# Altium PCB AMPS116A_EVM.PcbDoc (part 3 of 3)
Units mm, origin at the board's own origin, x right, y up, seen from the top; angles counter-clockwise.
Board outline 95 x 85 mm, 4 copper layers (Top Layer, Mid-Layer 1, Mid-Layer 2, Bottom Layer), stack 1.554 mm thick; 252 components, 134 nets, 806 pads, 625 vias.
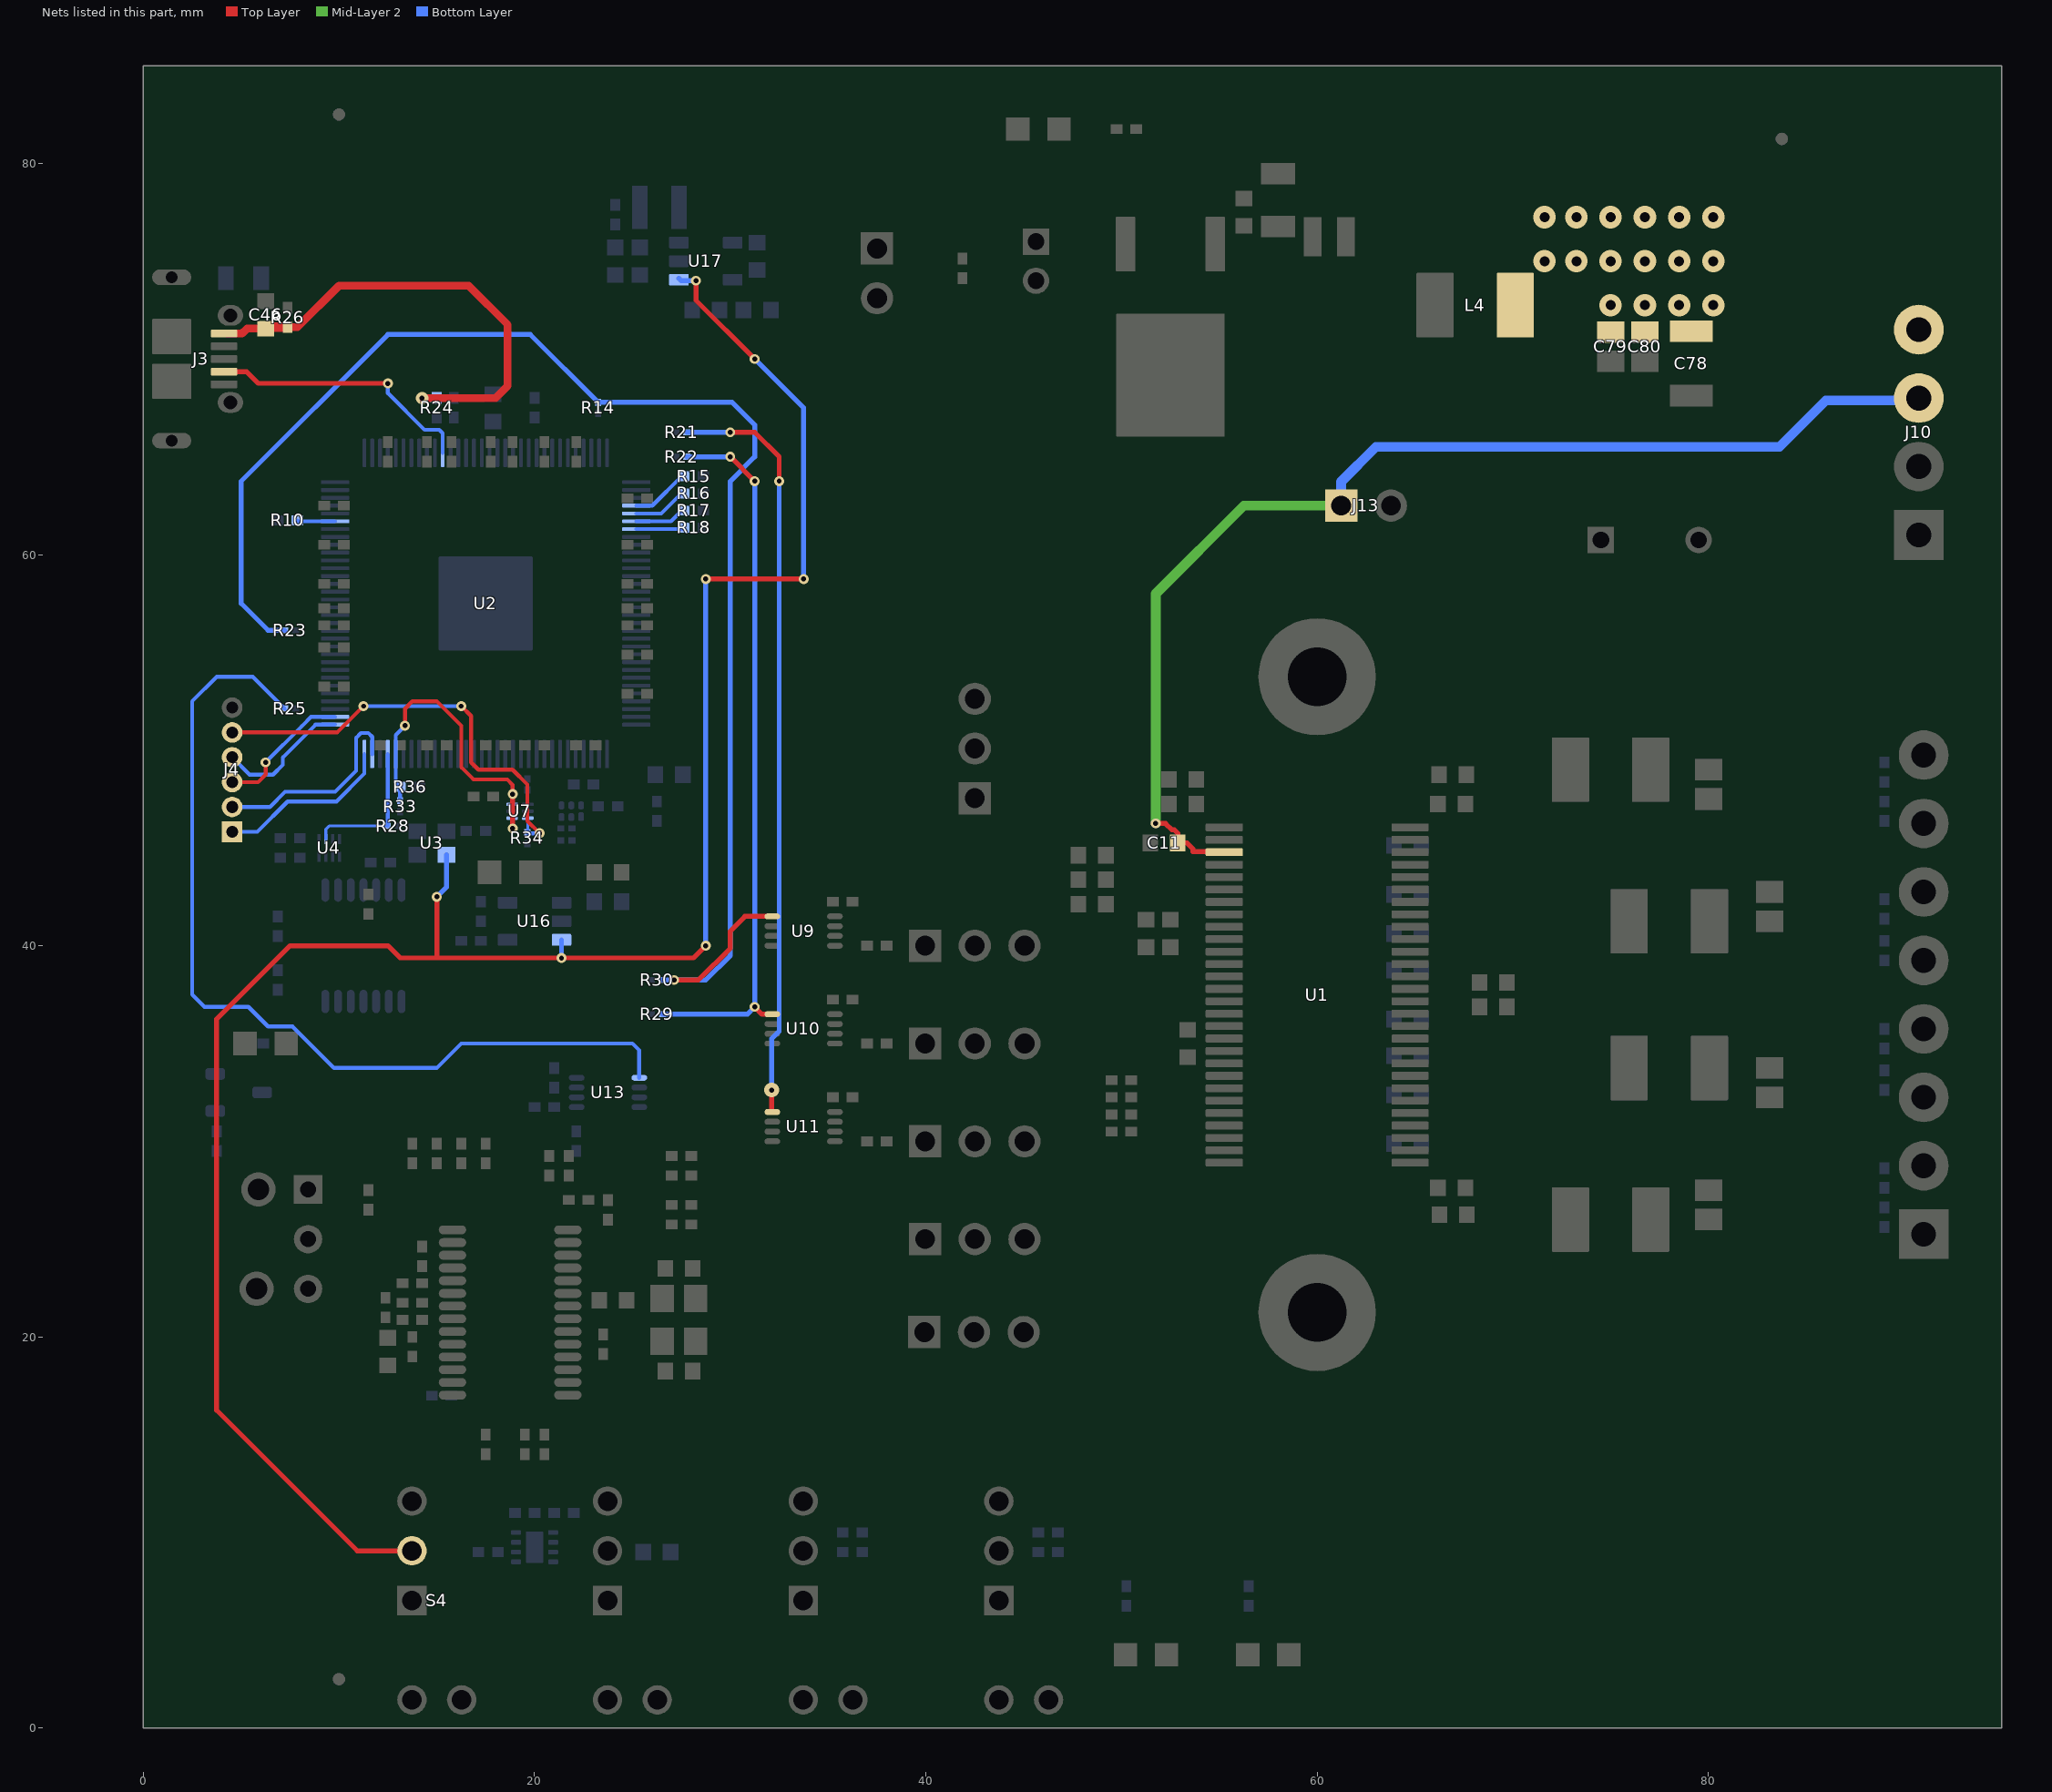
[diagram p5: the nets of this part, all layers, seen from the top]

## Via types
v1: diameter 0.508, hole 0.254, Top Layer to Bottom Layer, tented both sides, 516 vias
v2: diameter 0.762, hole 0.254, Top Layer to Bottom Layer, tented both sides, 30 vias
v3: diameter 1.143, hole 0.508, Top Layer to Bottom Layer, tented both sides, 28 vias
v4: diameter 0.889, hole 0.254, Top Layer to Bottom Layer, tented both sides, 24 vias
v5: diameter 0.6, hole 0.3, Top Layer to Bottom Layer, 12 vias
v6: diameter 0.635, hole 0.254, Top Layer to Bottom Layer, tented both sides, 9 vias
v7: diameter 6, hole 3.25, Top Layer to Bottom Layer, 4 vias
v8: diameter 0.5, hole 0.2, Top Layer to Bottom Layer, 2 vias

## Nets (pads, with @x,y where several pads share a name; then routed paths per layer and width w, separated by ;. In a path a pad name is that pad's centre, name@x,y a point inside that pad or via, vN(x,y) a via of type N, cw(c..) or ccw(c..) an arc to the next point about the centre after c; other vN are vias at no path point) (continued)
USB-EN: S4.2 U3.1 U16.3 U17.1 | length 108.6
  Top Layer w0.25: S4.2@13.73,9.065 10.935,9.065 3.75,16.25 3.75,36.25 7.5,40 12.5,40 13.125,39.375 15,39.375 ; v1(15,42.5) 15,39.375 ; v1(28.25,74) 28.25,73 v1(31.25,70) ; v1(28.75,40) 28.125,39.375 v1(21.375,39.375) 15,39.375 ; v1(28.75,58.75) v1(33.75,58.75)
  Bottom Layer w0.25: v1(15,42.5) 15.5,43 U3.1@15.5,44.65 ; v1(21.375,39.375) U16.3@21.375,40.3 ; U17.1@27.375,74.125 27.5,74 v1(28.25,74) ; v1(28.75,40) v1(28.75,58.75) ; v1(31.25,70) 33.75,67.5 v1(33.75,58.75)
USB-ID: J3.4 U2.43 | length 13.6
  Top Layer w0.25: J3.4@4.3,69.35 5.275,69.35 5.875,68.75 v1(12.5,68.75)
  Bottom Layer w0.2: v1(12.5,68.75) 12.5,68.25 14.375,66.375 15.125,66.375 15.3,66.2 U2.43@15.3,65.2
VBAT: C11.2 J10.3 J13.1 U1.3 | length 60
  Top Layer w0.254: v1(51.75,46.256) 52.244,46.256 ; 52.25,46.25 52.579,45.921 52.704,45.921 52.875,45.75 C11.2@52.875,45.25 53.358,45.25 53.647,44.96 53.647,44.803 U1.3@55.25,44.803
  Mid-Layer 2 w0.5: v1(51.75,46.256) 51.75,58 56.25,62.5 J13.1@61.23,62.5
  Bottom Layer w0.5: J13.1@61.23,62.5 61.23,63.73 63,65.5 83.625,65.5 86,67.875 J10.3@90.75,67.875
VBUS-IN: C46.1 J3.1 R24.2 R26.2 | length 24.4
  Top Layer w0.4: J3.1@4.3,71.3 5.05,71.3 5.3,71.55 C46.1@6.25,71.55 ; 7.625,71.625 7.875,71.625 10,73.75 16.625,73.75 18.625,71.75 18.625,68.625 18,68 v6(14.25,68)
  Top Layer w0.5: C46.1@6.25,71.55 6.325,71.625 R26.2@7.375,71.625
  Bottom Layer w0.4: v6(14.25,68) R24.2@15,68
VIN: C78.2 C79.2 C80.1 J10.4 L4.1
  other v3: 75,72.75 76.75,72.75 78.5,72.75 80.25,72.75 71.625,75 73.25,75 75,75 76.75,75 78.5,75 80.25,75 71.625,77.25 73.25,77.25 75,77.25 76.75,77.25 78.5,77.25 80.25,77.25
X-24M: R28.2 U2.125 U4.2 | length 7.4
  Bottom Layer w0.15: U4.2@9.325,45.45 9.325,45.95 9.5,46.125 R28.2@12.47,46.125
  Bottom Layer w0.2: R28.2@12.47,46.125 12.5,46.155 U2.125@12.5,49.8
X-BCLK: R22.2 R29.2 U10.1 | length 36.8
  Top Layer w0.25: v1(30,65) v1(31.25,63.75) ; v1(31.25,36.875) 31.625,36.5 U10.1@32.15,36.5 ; U10.1@32.225,36.5 U10.1@32.25,36.5
  Bottom Layer w0.25: R29.2@26.53,36.5 30.875,36.5 v1(31.25,36.875) v1(31.25,63.75) ; R22.2@27.78,65 v1(30,65)
X-DOUT: R25.2 U13.1 | length 47.4
  Bottom Layer w0.2: R25.2@7.22,52.125 5.595,53.75 3.75,53.75 2.5,52.5 2.5,37.5 3.125,36.875 5.375,36.875 6.375,35.875 7.625,35.875 9.75,33.75 15,33.75 16.25,35 25,35 25.35,34.65 U13.1@25.35,33.25
X-LRCK: R21.2 U11.1 | length 38.9
  Top Layer w0.25: v1(30,66.25) 31.25,66.25 32.5,65 v1(32.5,63.75) ; v2(32.125,32.625) 32.125,31.6 U11.1@32.225,31.5
  Bottom Layer w0.25: R21.2@27.78,66.25 v1(30,66.25) ; v2(32.125,32.625) 32.125,35.25 32.5,35.625 v1(32.5,63.75)
X-MCLK: R14.2 R23.2 R30.2 U9.1 | length 78.8
  Top Layer w0.25: v1(27.125,38.25) 28.375,38.25 30,39.875 30,40.75 30.75,41.5 U9.1@32.15,41.5
  Bottom Layer w0.25: R23.2@7.22,56.125 6.375,56.125 5,57.5 5,63.75 12.5,71.25 19.78,71.25 R14.2@23.25,67.78 30.095,67.78 31.25,66.625 31.25,65 30,63.75 30,39.5 28.75,38.25 v1(27.125,38.25) R30.2@26.53,38.25
X-QSPI-CS: R10.2 U2.27 | length 1.9
  Bottom Layer w0.2: R10.2@7.875,61.75 7.925,61.7 U2.27@9.8,61.7
X-RSTN: R33.2 R36.2 U2.124 U7.4 U7.6 | length 17
  Top Layer w0.2: v1(13.375,51.25) 13.375,52.125 13.75,52.5 15,52.5 16.25,51.25 16.25,49.125 16.875,48.5 18.6,48.5 18.875,48.225 v1(18.875,47.75)
  Top Layer w0.25: v1(18.875,46) v1(18.875,47.75)
  Bottom Layer w0.15: U7.4@18.85,46.525 18.875,46.5 v1(18.875,46) ; U7.6@18.85,47.225 18.875,47.25 v1(18.875,47.75)
  Bottom Layer w0.2: R33.2@13.125,47.405 R36.2@13.125,48.125 12.9,48.35 U2.124@12.9,49.8 12.9,50.775 v1(13.375,51.25)
X-SPI-SS0: R15.1 U2.68 | length 3
  Bottom Layer w0.2: U2.68@25.2,62.5 26.02,62.5 27.52,64 R15.1@27.625,64
X-SPI-SS1: R16.1 U2.69 | length 2.8
  Bottom Layer w0.2: U2.69@25.2,62.1 26.475,62.1 27.5,63.125 R16.1@27.625,63.125
X-SPI-SS2: R17.1 U2.70 | length 2.7
  Bottom Layer w0.2: U2.70@25.2,61.7 26.976,61.7 27.526,62.25 R17.1@27.625,62.25
X-SPI-SS3: R18.1 U2.71 | length 2.5
  Bottom Layer w0.2: U2.71@25.2,61.3 27.55,61.3 R18.1@27.625,61.375
X-TCK: J4.1 U2.128 | length 9
  Bottom Layer w0.2: J4.1@4.54,45.825 5.825,45.825 7.375,47.375 9.875,47.375 11.3,48.8 U2.128@11.3,49.8
X-TDI: J4.3 U2.2 | length 7
  Top Layer w0.2: J4.3@4.54,48.365 5.865,48.365 6.25,48.75 v1(6.25,49.375)
  Bottom Layer w0.2: v1(6.25,49.375) 8.125,51.25 8.575,51.7 U2.2@9.8,51.7
X-TDO: J4.4 U2.1 | length 6.9
  Bottom Layer w0.2: J4.4@4.54,49.635 5.425,48.75 6.625,48.75 7.125,49.25 7.125,49.625 8.8,51.3 U2.1@9.8,51.3
X-TMS: J4.2 U2.127 | length 10.7
  Bottom Layer w0.2: J4.2@4.54,47.095 6.47,47.095 7.25,47.875 9.809,47.875 10.875,48.941 10.875,50.625 11.125,50.875 11.5,50.875 11.7,50.675 U2.127@11.7,49.8
X-TRSTN: J4.5 R34.2 U7.3 | length 22.8
  Top Layer w0.2: J4.5@4.54,50.905 9.905,50.905 v1(11.25,52.25) ; v1(16.25,52.25) 16.75,51.75 16.75,49.375 17.125,49 18.875,49 19.625,48.25 19.625,46.375 v1(20.25,45.75)
  Bottom Layer w0.15: R34.2@19.625,45.78 19.65,45.805 U7.3@19.65,46.525
  Bottom Layer w0.2: v1(11.25,52.25) v1(16.25,52.25) ; R34.2@19.625,45.78 19.655,45.75 v1(20.25,45.75)
pads on no net: FID1.1 FID2.1 FID3.1 FID4.1 FID5.1 FID6.1 S1.1 S2.1 SH1.0 SH2.0 SH3.0 SH4.0 SH5.0 SH6.0 U2.4 U2.5 U2.7 U2.8 U2.9 U2.10 U2.12 U2.15 U2.18 U2.20 U2.21 U2.22 U2.23 U2.25 U2.26 U2.28 U2.30 U2.31 U2.32 U2.33 U2.34 U2.35 U2.39 U2.40 U2.50 U2.51 U2.53 U2.54 U2.57 U2.58 U2.59 U2.61 U2.62 U2.65 U2.72 U2.74 U2.75 U2.76 U2.77 U2.79 U2.82 U2.84 U2.85 U2.86 U2.88 U2.89 U2.90 U2.91 U2.93 U2.94 U2.95 U2.96 U2.97 U2.98 U2.99 U2.100 U2.106 U2.107 U2.108 U2.109 U2.112 U2.113 U2.114 U2.115 U2.117 U2.118 U2.119 U2.121 U2.122 U4.6 U5.4 U5.8 U5.14 U9.3 U10.3 U11.3 U12.1 U12.2 U12.3 U12.9 U12.15 U12.16 U12.17 U12.18 U13.3 U14.0 U15.4@50.505,70.35 U15.4@50.505,71.53 U15.4@51.835,70.35 U15.4@51.835,71.53 U15.4@53.165,70.35 U15.4@53.165,71.53 U15.4@54.495,70.35 U15.4@54.495,71.53 U15.5 U15.6 U15.7

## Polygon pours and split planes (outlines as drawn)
PVDD on Mid-Layer 2 "PVDD Copper Layer 3" (solid, remove dead copper, pour order 152): 68.75,70 68.75,68.25 74.75,62.25 75.75,62.25 76,62 76,56 65.75,45.75 65.75,26.875 65.375,26.5 64,26.5 60,30.5 60,43.75 59.25,44.5 56.75,44.5 56.375,44.875 56.375,46 56.75,46.375 60.125,46.375 70.75,57 70.75,60 69.5,61.25 63.75,61.25 62.875,62.125 62.875,70.125 63.625,70.875 67.875,70.875
3.3V on Mid-Layer 2 "3.3V Copper Layer 3" (solid, remove dead copper, pour order 180): 39.375,77.5 16.5,77.5 5,66 5,57 6.25,55.75 6.25,41.25 7.5,40 27.5,40 29.875,42.375 29.875,59.875 40.375,70.375 40.375,76.5
1.0V on Mid-Layer 2 "1.0V Copper Layer 3" (solid, remove dead copper, pour order 177): 22.75,76.25 20.875,76.25 20.5,75.875 20.5,66.75 20,66.25 11.25,66.25 8.75,63.75 8.75,51.25 11,49 24,49 26.25,51.25 26.25,61 26,61.25 24.5,61.25 24.25,61 24.25,51.75 23.25,50.75 11.75,50.75 10.75,51.75 10.75,63 12.25,64.5 22.25,64.5 23.125,65.375 23.125,75.875
GND on Mid-Layer 2 "GND Copper Layer 3" (solid, remove dead copper, pour order 206): 0.5,83 2,84.5 93,84.5 94.5,83 94.5,2 93,0.5 2,0.5 0.5,2
VIN on Top Layer "VIN Top Layer" (solid, remove dead copper, pour order 204): 71.5,78.125 88.625,78.125 92.25,74.5 92.25,70.375 91.875,70 89.375,70 88.5,70.875 70.5,70.875 70.5,77.125
OUT3- on Top Layer "OUT3- Top Copper" (solid, remove dead copper, pour order 197): 79.85,43 81.75,43 81.75,42.475 82.425,41.8 83.95,41.8 85.625,40.125 91.25,40.125 91.25,38.375 84.875,38.375 83.75,39.5 79.85,39.5
OUT3+ on Top Layer "OUT3+ Top Copper" (solid, remove dead copper, pour order 196): 76.85,50.75 81.75,50.75 88.875,43.625 91.25,43.625 91.25,41.875 88.125,41.875 81.55,48.45 79.3,48.45 78.75,47.9 78.75,47.25 76.85,47.25
OUT3M on Top Layer "OUT3M Top Copper" (solid, remove dead copper, pour order 195): 63.8,39.175 63.925,39.3 65.29,39.3 74.25,41.105 74.25,43 76.125,43 76.125,39.5 75.375,38.75 65.75,38.75 65.625,38.875 63.925,38.875 63.8,39
OUT3P on Top Layer "OUT3P Top Copper" (solid, remove dead copper, pour order 194): 63.8,40.275 63.925,40.15 66.525,40.15 66.6,40.225 67.075,40.225 69.75,40.875 73.125,46.625 73.125,50.75 71.25,50.75 71.25,47.25 68.25,41.625 66.525,41.5 65.708,40.575 63.925,40.575 63.8,40.45
OUT4P on Top Layer "OUT4P Top Copper" (solid, remove dead copper, pour order 193): 63.8,44.075 63.925,43.95 66.7,43.95 67.05,44.3 67.677,44.3 68.375,44.975 68.375,45.375 68,45.75 67.5,46.25 66.75,46.25 65.875,45.375 65.875,44.75 65.875,44.5 65.75,44.375 63.925,44.375 63.8,44.25
OUT4M on Top Layer "OUT4M Top Copper" (solid, remove dead copper, pour order 192): 63.8,43 63.925,43.125 66.225,43.125 67.175,44.075 67.575,44.075 67.825,43.825 67.825,42.425 67.55,42.15 66.2,42.15 65.675,42.675 63.925,42.675 63.8,42.8
1.0V on Top Layer "1.0V Top Copper" (solid, remove dead copper, pour order 176): 20.875,76.25 20.5,75.875 20.5,74.875 20.875,74.5 22.625,74.5 23,74.875 23,75.875 22.625,76.25
3.3V on Top Layer "3.3V Top Copper" (solid, remove dead copper, pour order 179): 36.625,74.75 43.5,74.75 44,75.25 48.75,75.25 49.625,74.375 50.625,74.375 50.75,74.5 50.75,77.25 50.625,77.375 37.5,77.375 36.625,76.5
PVDD on Top Layer "PVDD Top Copper" (solid, remove dead copper, pour order 145): 63.625,66.625 62,68.25 62,74.25 61,75.25 61,77.25 62.375,77.25 65.75,73.875 65.75,70.875 67.875,70.875 68.625,70.125 68.625,67.375 67.875,66.625
OUT2- on Top Layer "OUT2- Top Copper" (solid, remove dead copper, pour order 143): 76.85,24.25 81.75,24.25 88.875,31.375 91.25,31.375 91.25,33.125 88.125,33.125 81.55,26.55 79.3,26.55 78.75,27.1 78.75,27.75 76.85,27.75
OUT2+ on Top Layer "OUT2+ Top Copper" (solid, remove dead copper, pour order 142): 79.85,32 81.75,32 81.75,32.525 82.425,33.2 83.95,33.2 85.625,34.875 91.25,34.875 91.25,36.625 84.875,36.625 83.75,35.5 79.85,35.5
OUT2M on Top Layer "OUT2M Top Copper" (solid, remove dead copper, pour order 139): 63.8,34.725 63.925,34.85 66.525,34.85 66.6,34.775 67.075,34.775 69.75,34.125 73.125,28.375 73.125,24.25 71.25,24.25 71.25,27.75 68.25,33.375 66.525,33.5 65.708,34.425 63.925,34.425 63.8,34.55
OUT2P on Top Layer "OUT2P Top Copper" (solid, remove dead copper, pour order 138): 63.8,35.825 63.925,35.7 65.321,35.7 72.762,34.232 74.25,32 76.125,32 76.125,35.5 75.375,36.25 65.75,36.25 65.625,36.125 63.925,36.125 63.8,36
PVDD on Top Layer "PVDD Top Copper" (solid, remove dead copper, pour order 150): 65.6,29.775 65.75,29.625 65.75,29 66.625,28.125 66.625,25.75 64.25,25.75 63.75,26.25 63.75,29.6 63.925,29.775
PVDD on Top Layer "PVDD Top Copper" (solid, remove dead copper, pour order 149): 68.875,38.025 62.6,38.025 62.125,38.5 60.375,38.5 60.125,38.25 60.125,36.75 60.375,36.5 62.125,36.5 62.6,36.975 68.875,36.975
OUT1P on Top Layer "OUT1P Top Copper" (solid, remove dead copper, pour order 134): 63.8,32 63.925,31.875 66.225,31.875 67.175,30.925 67.575,30.925 67.825,31.175 67.825,32.575 67.55,32.85 66.2,32.85 65.675,32.325 63.925,32.325 63.8,32.2
OUT1M on Top Layer "OUT1M Top Copper" (solid, remove dead copper, pour order 136): 63.8,30.925 63.925,31.05 66.7,31.05 67.05,30.7 67.677,30.7 68.375,30.025 68.375,29.625 68,29.25 67.5,28.75 66.75,28.75 65.875,29.625 65.875,30.25 65.875,30.5 65.75,30.625 63.925,30.625 63.8,30.75
GND-USB on Top Layer "GND-USB Top Copper" (solid, remove dead copper, pour order 190): 3.55,67.5 3.55,68.75 3.7,68.9 4.9,68.9 4.9,67.65 4.75,67.5
PVDD on Top Layer "PVDD Top Copper" (solid, remove dead copper, pour order 146): 65.6,45.225 65.75,45.375 65.75,46 66.625,46.875 66.625,49.25 64,49.25 63.75,49 63.75,45.4 63.925,45.225
PVDD on Top Layer "PVDD Top Copper" (solid, remove dead copper, pour order 147): 56.725,44.6 57.025,44.6 57.275,44.85 57.275,46.025 57.025,46.275 56.725,46.275 56.475,46.025 56.475,45.85 56.275,45.65 54.4,45.65 54.275,45.525 54.275,45.3 54.35,45.225 56.275,45.225 56.475,45.025 56.475,44.85
PVDD-VR on Top Layer "PVDD-VR Top Copper" (solid, remove dead copper, pour order 144): 54.25,77.25 54.375,77.375 60.125,77.375 60.25,77.25 60.25,75.25 57.25,75.25 56.375,74.375 54.375,74.375 54.25,74.5
GND on Top Layer "GND Top Copper" (solid, remove dead copper, pour order 207): 1.045,83.08 2.545,84.58 93.545,84.58 95.045,83.08 95.045,2.08 93.545,0.58 2.545,0.58 1.045,2.08
PVDD on Top Layer "PVDD Top Copper" (solid, remove dead copper, pour order 148): 75.75,62.25 76,62 76,59.5 75.75,59.25 73.25,59.25 73,59.5 73,62 73.25,62.25
no net on Bottom Layer "BOTTOM_LAYER_NONET_P203" (solid, remove dead copper, pour order 203): 81,78
VIN on Bottom Layer "VIN Bottom Layer" (solid, remove dead copper, pour order 202): 71.5,78.125 88.625,78.125 92.25,74.5 92.25,70.5 91.75,70 89.375,70 88.625,70.75 71.625,70.75 70.875,71.5 70.875,77.5
OUT4M on Bottom Layer "OUT4M Bottom Copper" (solid, remove dead copper, pour order 201): 65.875,42.5 65.875,42.875 67.125,44.125 68.125,44.125 70,42.25 76.125,42.25 76.125,40.25 69.25,40.25 67.375,42.125 66.25,42.125
OUT4P on Bottom Layer "OUT4P Bottom Copper" (solid, remove dead copper, pour order 200): 65.875,44.875 66.125,44.625 66.25,44.5 71.75,44.5 73.125,45.875 73.125,50.75 71.25,50.75 71.25,46.875 70.875,46.5 67,46.5 65.875,45.375
OUT4+ on Bottom Layer "OUT4+ Bottom Copper" (solid, remove dead copper, pour order 199): 76.85,47.25 78.75,47.25 78.75,47.9 79.3,48.45 80.7,48.45 81.25,49 91.5,49 91.5,50.75 76.85,50.75
OUT4- on Bottom Layer "OUT4- Bottom Copper" (solid, remove dead copper, pour order 198): 79.85,39.5 84.5,39.5 90,45 91.125,45 91.125,46.75 88.75,46.75 88.75,46.25 84.3,41.8 82.425,41.8 81.75,42.475 81.75,43 79.85,43
1.0V on Bottom Layer "1.0V Bottom Copper" (solid, remove dead copper, pour order 178): 25.875,78.875 25.875,75.25 23.375,75.25 22.625,74.5 20.875,74.5 20.5,74.875 20.5,75.875 20.875,76.25 22.25,76.25 23.25,77.25 24.625,77.25 24.875,77.5 24.875,78.875
SW on Bottom Layer "SW-VR Bottom Copper" (solid, remove dead copper, pour order 166): 26.875,75.65 26.875,78.75 26.975,78.85 27.775,78.85 27.875,78.75 27.875,75.65
3.3V on Bottom Layer "3.3V Bottom Copper" (solid, remove dead copper, pour order 181): 31.75,77.125 32,76.875 32,75.625 31.875,75.5 29.75,75.5 29.625,75.625 29.625,76.625 30.125,77.125
PVDD on Bottom Layer "PVDD Bottom Copper" (solid, remove dead copper, pour order 165): 67.875,70.875 68.625,70.125 68.625,67.375 67.875,66.625 63.625,66.625 62.875,67.375 62.875,70.125 63.625,70.875
3.3V on Bottom Layer "3.3V Bottom Copper" (solid, remove dead copper, pour order 184): 36.625,74.75 43.5,74.75 44,75.25 47.25,75.25 47.75,74.75 49.5,74.75 49.75,75 49.75,77.125 49.5,77.375 37.5,77.375 36.625,76.5
OUT1+ on Bottom Layer "OUT1+ Bottom Copper" (solid, remove dead copper, pour order 140): 79.85,35.5 84.5,35.5 90,30 91.125,30 91.125,28.25 88.75,28.25 88.75,28.75 84.3,33.2 82.425,33.2 81.75,32.525 81.75,32 79.85,32
OUT1- on Bottom Layer "OUT1- Bottom Copper" (solid, remove dead copper, pour order 141): 76.85,27.75 78.75,27.75 78.75,27.1 79.3,26.55 80.7,26.55 81.25,26 91.5,26 91.5,24.25 76.85,24.25
OUT1M on Bottom Layer "OUT1M Bottom Copper" (solid, remove dead copper, pour order 137): 65.875,30.125 66.125,30.375 66.25,30.5 71.75,30.5 73.125,29.125 73.125,24.25 71.25,24.25 71.25,28.125 70.875,28.5 67,28.5 65.875,29.625
OUT1P on Bottom Layer "OUT1P Bottom Copper" (solid, remove dead copper, pour order 135): 65.875,32.5 65.875,32.125 67.125,30.875 68.125,30.875 70,32.75 76.125,32.75 76.125,34.75 69.25,34.75 67.375,32.875 66.25,32.875
GND-USB on Bottom Layer "GND-USB Bottom Copper" (solid, remove dead copper, pour order 191): 3.75,74.75 3.55,74.55 3.55,72.5 4.75,72.5 4.75,74.625 4.625,74.75
PVDD on Bottom Layer "PVDD Bottom Copper" (solid, remove dead copper, pour order 162): 75.75,62.25 76,62 76,59.5 75.75,59.25 73.25,59.25 73,59.5 73,62 73.25,62.25
GND on Bottom Layer "GND Bottom Copper" (solid, remove dead copper, pour order 205): 0.796,83.345 2.296,84.845 93.296,84.845 94.796,83.345 94.796,2.345 93.296,0.845 2.296,0.845 0.796,2.345
3.3V on Bottom Layer "3.3V Bottom Copper" (solid, remove dead copper, pour order 182): 20.675,8.6 20.675,7.55 20.875,7.35 21.175,7.35 21.375,7.55 21.375,8.45 21.2,8.625 20.7,8.625
3.3V-SPDIF on Bottom Layer "3.3V-SPDIF Bottom Copper" (solid, remove dead copper, pour order 185): 19.325,9.375 18.7,9.375 17.6,10.475 17.6,10.9 17.95,11.25 19.325,11.25
3.3V on Bottom Layer "3.3V Bottom Copper" (solid, remove dead copper, pour order 183): 20.675,9.4 20.675,11.925 20.875,12.125 21.125,12.125 21.375,11.875 21.375,9.55 21.2,9.375 20.7,9.375
PVDD on Mid-Layer 1 "PVDD Copper Layer 2" (solid, remove dead copper, pour order 151): 75.75,62.25 76,62 76,59.5 75.75,59.25 73.25,59.25 73,59.5 73,62 73.25,62.25
PVDD on Mid-Layer 1 "VIN Copper Layer 2" (solid, remove dead copper, pour order 168): 63.625,70.875 62.875,70.125 62.875,67.375 63.625,66.625 67.875,66.625 68.625,67.375 68.625,70.125 67.875,70.875
GND on Mid-Layer 1 "GND Copper Layer 2" (solid, remove dead copper, pour order 208): 0.5,83 2,84.5 93,84.5 94.5,83 94.5,2 93,0.5 2,0.5 0.5,2

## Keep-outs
Keep-Out Layer:
  lines w0.254: -0.25,-0.25 95.25,-0.25 95.25,85.25 -0.25,85.25 -0.25,-0.25

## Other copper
Top Layer:
  text ".Layer_Name" at 14.656,-46.806 h1.52
Mid-Layer 1:
  text ".Layer_Name" at 14.656,-46.806 h1.52
Mid-Layer 2:
  text ".Layer_Name" at 14.656,-46.806 h1.52
Bottom Layer:
  text ".Layer_Name" at 14.656,-46.806 h1.52

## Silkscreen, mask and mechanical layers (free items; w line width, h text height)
Top Overlay:
  region: 86.875,3.75 76.875,3.75 76.875,1.25 86.875,1.25
  lines w0.2: 46.375,43.875 47,43.375
  lines w0.25: 38.375,18.375 38.375,17.875 41.625,17.875 41.625,18.375 ; 39.125,50.25 40.625,50.25 ; 39.375,49.75 40.375,49.75 ; 39.625,49.25 40.125,49.25 ; 39.875,50.25 39.875,50.5 ; 42.625,18.375 42.625,17.875 45.875,17.875 45.875,18.375 ; 46.75,20.125 48.25,20.125 ; 46.75,25.25 48.25,25.25 ; 46.75,30.25 48.25,30.25 ; 46.75,35.25 48.25,35.25 ; 46.75,40.25 48.25,40.25 ; 47,19.625 48,19.625 ; 47,24.75 48,24.75 ; 47,29.75 48,29.75 ; 47,34.75 48,34.75 ; 47,39.75 48,39.75 ; 47.25,19.125 47.75,19.125 ; 47.25,24.25 47.75,24.25 ; 47.25,29.25 47.75,29.25 ; 47.25,34.25 47.75,34.25 ; 47.25,39.25 47.75,39.25 ; 47.5,20.125 47.5,20.375 ; 47.5,25.25 47.5,25.5 ; 47.5,30.25 47.5,30.5 ; 47.5,35.25 47.5,35.5 ; 47.5,40.25 47.5,40.5 ; 87.25,60.75 87.25,59.5 87.75,59.5 ; 87.25,65 87.25,66.25 87.75,66.25
  lines w0.3: 86.5,25.25 87.5,25.25
  text "3.3V" at 31.5,74.875 h1.5
  text "GND" at 31.875,72.375 h1.5
  text "PVDD" at 83.375,71 h1.25
  text "VBAT" at 83.25,67.25 h1.25
  text "GND" at 87.75,61.25 h1.25 r90
  text "I2C" at 41.375,54.625 h1.5
  text "SDA" at 36.75,52 h1.5
  text "4+" at 85.25,48.875 h1.5
  text "SCL" at 36.875,46.75 h1.5
  text "4-" at 85.25,45.625 h1.5
  text "3+" at 85.25,41.875 h1.5
  text "USB" at 16.75,40.75 h1.5
  text "READY" at 15.625,38.625 h1.5
  text "3-" at 85.25,38.625 h1.5
  text "2+" at 85.25,35 h1.5
  text "SPDIF" at 0.75,32.125 h1.5
  text "LOCK" at 7,32.125 h1.5
  text "2-" at 85.25,31.75 h1.5
  text "1+" at 85.25,28 h1.5
  text "1" at 85.25,24.5 h1.5
  text "I2S" at 38.875,16.125 h1.25
  text "PSIA" at 42.375,16.125 h1.25
  text "UP=ENABLE" at 15.125,11.5 h0.9
  text "UP=NORM" at 35,11.25 h1
  text "UP=ON" at 25,11 h1.25
  text "UP=NORM" at 45,11 h1.25
  text "DN=DISABLE" at 15.125,10.25 h0.9
  text "DN=STBY" at 35,9.75 h1
  text "DN=OFF" at 25,9.25 h1.25
  text "DN=MUTE" at 45,9 h1.25
  text "XMOS" at 15,8 h1
  text "SPDIF" at 25.125,6.625 h1.15
  text "MUTE" at 45.125,6.625 h1.15
  text "STANDBY" at 35,6.6 h1.15
  text "ENABLE" at 15,6.5 h1
  text ".EVM_Orderable" at 62.5,4.625 h2
  text "-" at 74.875,2 h1.52
  text ".PRJ_Number" at 63.375,1.875 h1.5
  text ".PCB_Rev" at 72.625,1.875 h1.5
  text ".Layer_Name" at 14.656,-46.806 h1.52
Bottom Overlay:
  lines w0.25: 28.375,65.375 28.875,65.875
  text ".Layer_Name" at 14.656,-46.806 h1
Top Paste:
  text ".Layer_Name" at 14.656,-46.806 h1.52
Bottom Paste:
  text ".Layer_Name" at 14.656,-46.806 h1.52
Top Solder:
  text ".Layer_Name" at 14.656,-46.806 h1.52
Bottom Solder:
  text ".Layer_Name" at 14.656,-46.806 h1.52
Drill Guide:
  text ".Layer_Name" at 0.25,165.625 h1.52
M1 Board Outline:
  the board outline again, w0.254
  text ".Layer_Name" at 57,-46.875 h1.52
M2 Board Dimensions:
  text ".Layer_Name" at 99.625,-46.875 h1.52
M3 3D STEP Top:
  text ".Layer_Name" at 14.656,-46.806 h1.52
M4 3D STEP Bottom:
  text ".Layer_Name" at 14.656,-46.806 h1.52
M5 Assembly Top:
  lines w0.254: -7.417,-48.626 160.223,-48.626 ; -7.417,-43.462 160.274,-43.462 ; -7.417,-38.297 -7.417,-53.791 94.31,-53.791 160.274,-53.791 160.274,-38.297 -7.404,-38.297 -7.404,-53.791 32.614,-53.791 ; 55.194,-53.791 55.194,-38.297 ; 87.376,-43.462 87.376,-38.297 ; 108.712,-43.462 108.712,-38.297 ; 124.511,-53.956 124.511,-48.804
  text "COMPONENTS MARKED 'DNP' SHOULD NOT BE POPULATED." at 29.299,-33.09 h1.52
  text "ASSEMBLY VARIANT:" at 29.286,-36.024 h1.52
  text ".VariantName" at 55.601,-36.024 h1.52
  text "PCB VIEWED FROM TOP SIDE" at -5.804,-41.654 h1.52
  text "BOARD #:" at 57.099,-41.654 h1.52
  text ".PRJ_Number" at 70.955,-41.654 h1.52
  text "REV:" at 92.405,-41.654 h1.52
  text ".PCB_Rev" at 99.809,-41.654 h1.52
  text "SVN REV:" at 113.69,-41.654 h1.52
  text ".VersionControl_RevNumber" at 126.543,-41.654 h1.52
  text "PLOT NAME =" at -5.804,-52.034 h1.52
  text ".plot_File_Name" at 14.656,-52.034 h1.52
  text "GENERATED    :" at 57.15,-52.034 h1.52
  text ".Print_Date" at 79.235,-52.034 h1.52
  text ".Print_Time" at 97.752,-52.034 h1.52
  text "TEXAS INSTRUMENTS" at 129.87,-52.034 h1.52
M6 Assembly Bottom:
  lines w0.254: -7.429,-43.474 160.261,-43.474 ; -7.379,-48.639 160.261,-48.639 ; 28.334,-53.969 28.334,-48.817 ; 44.133,-43.474 44.133,-38.31 ; 65.468,-43.474 65.468,-38.31 ; 97.65,-53.804 97.65,-38.31 ; 120.231,-53.804 160.249,-53.804 160.249,-38.31 -7.429,-38.31 -7.429,-53.804 58.534,-53.804 160.261,-53.804 160.261,-38.31
  text "COMPONENTS MARKED 'DNP' SHOULD NOT BE POPULATED." at 154.991,-33.077 h1.52
  text ".VariantName" at 128.473,-36.024 h1.52
  text "ASSEMBLY VARIANT:" at 154.864,-36.024 h1.52
  text ".VersionControl_RevNumber" at 26.302,-41.667 h1.52
  text "SVN REV:" at 39.154,-41.667 h1.52
  text ".PCB_Rev" at 53.035,-41.667 h1.52
  text "REV:" at 60.439,-41.667 h1.52
  text ".PRJ_Number" at 81.89,-41.667 h1.52
  text "BOARD #:" at 95.745,-41.667 h1.52
  text "PCB VIEWED FROM BOTTOM SIDE" at 158.648,-41.667 h1.52
  text "TEXAS INSTRUMENTS" at 22.974,-52.047 h1.52
  text ".Print_Time" at 55.093,-52.047 h1.52
  text ".Print_Date" at 73.609,-52.047 h1.52
  text "GENERATED    :" at 95.694,-52.047 h1.52
  text ".plot_File_Name" at 138.189,-52.047 h1.52
  text "PLOT NAME =" at 158.648,-52.047 h1.52
M9 Title Sheet:
  drawing of 57 lines, arcs and shapes, not listed
  text "1" at 18.792,179.127 h1.78
  text "2" at 82.182,179.127 h1.78
  text "3" at 145.411,179.127 h1.78
  text "4" at 209.08,179.127 h1.78
  text "5" at 272.555,179.127 h1.78
  text "6" at 336.182,179.127 h1.78
  text "A" at -10.579,150.095 h1.78
  text "A" at 365.341,150.095 h1.78
  text "B" at -10.579,89.643 h1.78
  text "B" at 365.341,89.643 h1.78
  text "C" at -10.579,29.318 h1.78
  text "C" at 365.341,29.318 h1.78
  text "PROJECT TITLE:" at 288.125,-17.952 h1.14
  text ".PRJ_Title" at 289.395,-21.338 h1.78
  text "DESIGNED FOR:" at 288.125,-25.597 h1.14
  text ".PRJ_Customer" at 289.395,-29.153 h1.78
  text "D" at -10.579,-30.88 h1.78
  text "D" at 365.341,-30.88 h1.78
  text "FILE NAME:" at 288.125,-33.217 h1.14
  text ".PCB_File_Name_No_Path" at 289.395,-36.265 h1.78
  text "Texas Instruments (TI) and/or its licensors do not warrant the accuracy or completeness of this specification" at 161.9,-40.376 h1.14
  text "ENGINEER:" at 288.125,-40.583 h1.14
  text "LAYOUT BY:" at 326.352,-40.583 h1.14
  text "or any information contained therein. TI and/or its licensors do not warrant that this design will meet" at 160.757,-43.237 h1.14
  text ".PRJ_Engineer" at 289.395,-44.52 h1.78
  text ".PCB_Layout" at 327.635,-44.52 h1.78
  text "the specifications, will be suitable for your application or fit for any particular purpose, or will operate in" at 160.757,-46.099 h1.14
  text "ALTIUM DESIGNER VERSION:" at 326.352,-48.457 h1.14
  text "an implementation. TI and/or its licensors do not warrant that the design is production worthy. You should" at 160.757,-48.961 h1.14
  text "completely validate and test your design implementation to confirm the system functionality for your application." at 161.9,-51.822 h1.14
  text ".print_Scale" at 289.395,-51.843 h1.78
  text ".Application_BuildNumber" at 327.635,-51.843 h1.78
  text "1" at 18.792,-57.093 h1.78
  text "2" at 82.182,-57.093 h1.78
  text "3" at 145.411,-57.093 h1.78
  text "4" at 209.08,-57.093 h1.78
  text "5" at 272.555,-57.093 h1.78
  text "6" at 336.182,-57.093 h1.78
M10 Fab Notes:
  drawing of 189 lines, arcs and shapes, not listed
  text ".Layer_Name" at 287.375,139.875 h1.52
  text "DESIGN INFORMATION" at 314.503,136.447 h1.52
  text "MIN. TRACK WIDTH:" at 298.131,133.091 h1.52
  text "8" at 325.976,133.091 h1.52
  text "MIL" at 329.907,133.091 h1.52
  text "MIN. CLEARANCE:" at 298.131,129.938 h1.52
  text "0.2" at 324.452,129.938 h1.52
  text "mm" at 329.907,129.938 h1.52
  text "MIN. VIA PAD SIZE:" at 298.131,126.785 h1.52
  text "20" at 325.214,126.785 h1.52
  text "MIL" at 329.907,126.785 h1.52
  text "0.05mm (2MIL)" at 315.784,123.486 h1.52
  text "MINIMUM ANNULAR RING" at 289.769,123.277 h1.52
  text "EXTERNAL" at 333.768,123.277 h1.52
  text "PER" at 294.849,120.48 h1.52
  text "IPC-D-275 CLASS 2 LEVEL C" at 300.437,120.48 h1.52
  text "MIL, HOLES" at 338.238,117.928 h1.52
  text "+/-" at 328.27,117.709 h1.52
  text "+/-" at 349.961,117.709 h1.52
  text "REGISTRATION TOLERANCES:" at 289.769,117.682 h1.52
  text "METAL" at 320.243,117.682 h1.52
  text "5" at 334.879,117.683 h1.52
  text "3" at 356.037,117.683 h1.52
  text "MIL" at 358.99,117.682 h1.52
  text "HOLE SIZE TOLERANCE (UNLESS OTHERWISE SPECIFIED):" at 289.769,115.185 h1.52
  text "+/-" at 349.961,115.112 h1.52
  text "3" at 356.037,115.085 h1.52
  text "MIL" at 358.99,115.085 h1.52
  text "MATERIAL:" at 287.87,111.589 h1.52
  text "FR-4 High Tg" at 312.926,108.324 h1.52
  text "X" at 309.257,108.122 h1.52
  text "FR-408" at 298.563,108.007 h1.52
  text "OTHER" at 336.358,108.007 h1.52
  text "62 MIL (1.6mm) +/-10%" at 306.694,104.374 h1.52
  text "X" at 303.643,104.312 h1.52
  text "THICKNESS:" at 289.769,104.165 h1.52
  text "OTHER" at 339.33,104.165 h1.52
  text "TOLERANCE:" at 289.769,100.652 h1.52
  text "X" at 311.314,100.652 h1.52
  text "ANSI IPC-6012 TYPE 3 CLASS 2" at 315.836,100.652 h1.52
  text "OTHER +/-" at 315.835,96.989 h1.52
  text "BOW & TWIST:" at 289.769,93.302 h1.52
  text "X" at 311.314,93.302 h1.52
  text "ANSI IPC-6012 TYPE 3 CLASS 2" at 315.836,93.302 h1.52
  text "OTHER +/-" at 315.835,89.576 h1.52
  text "DRILLING:" at 287.87,86.258 h1.52
  text "NC_DRILL FILES" at 332.599,83.586 h1.52
  text "REFERENCE:" at 289.769,83.486 h1.52
  text "X" at 306.463,83.484 h1.52
  text "AS SHOWN" at 310.984,83.486 h1.52
  text "X" at 329.348,83.486 h1.52
  text "OTHER" at 340.168,79.873 h1.52
  text "PTH COPPER THICKNESS:" at 289.761,79.783 h1.52
  text "X" at 318.697,79.783 h1.52
  text "20-30 um" at 321.948,79.783 h1.52
  text "BOARD FINISH:" at 287.87,76.034 h1.52
  text "SILKSCREEN:" at 291.812,73.237 h1.52
  text "X" at 316.14,73.237 h1.52
  text "TOP" at 319.112,73.237 h1.52
  text "X" at 329.094,73.237 h1.52
  text "BOTTOM" at 332.091,73.237 h1.52
  text "SILKSCREEN COLOR:" at 291.812,69.295 h1.52
  text "X" at 316.115,69.295 h1.52
  text "WHITE" at 319.112,69.295 h1.52
  text "OTHER" at 332.091,69.295 h1.52
  text "X" at 319.442,65.652 h1.52
  text "BLUE" at 322.439,65.652 h1.52
  text "OTHER" at 338.136,65.652 h1.52
  text "SOLDER RESIST COLOR:" at 291.812,65.477 h1.52
  text "X" at 319.442,61.734 h1.52
  text "MATTE" at 322.439,61.734 h1.52
  text "SEMI-GLOSS" at 338.125,61.717 h1.52
  text "IMMERSION GOLD (ENIG)" at 314.819,57.345 h1.52
  text "ENEPIG" at 348.793,57.162 h1.52
  text "SURFACE FINISH:" at 287.87,57.136 h1.52
  text "X" at 310.298,57.136 h1.52
  text "IMM. TIN/SILVER OR EQUIV" at 296.24,53.649 h1.52
  text "OTHER" at 332.599,53.549 h1.52
  text "ARRAY/PANEL:" at 287.87,49.602 h1.52
  text "CUT AND TRIM PER M1 BOARD OUTLINE" at 314.819,49.393 h1.52
  text "N.C. ROUTE" at 314.819,45.94 h1.52
  text "X" at 332.295,45.94 h1.52
  text "V. SCORE" at 336.816,45.94 h1.52
  text "CERTIFICATION:" at 287.87,42.66 h1.52
  text "MATERIALS AND WORKMANSHIP FOR ALL PCBS" at 306.285,42.66 h1.52
  text "TO MEET OR EXCEED THE REQUIREMENTS OF:" at 306.285,40.271 h1.52
  text "X" at 297.078,37.003 h1.52
  text "ANSI IPC-A-600F CLASS ->" at 300.329,37.003 h1.52
  text "X" at 342.188,37.003 h1.52
  text "2" at 344.982,37.003 h1.52
  text "1" at 336.981,36.965 h1.52
  text "3" at 353.973,36.965 h1.52
  text "X" at 317.702,33.252 h1.52
  text "RoHS" at 320.953,33.252 h1.52
  text "OTHER" at 337.321,33.252 h1.52
  text "PER ORDER" at 347.407,33.252 h1.52
  text "ALL BOARDS MUST MEET OR EXCEED UL94-V0 REQUIREMENTS." at 288.569,29.345 h1.52
  text "PCB MUST BEAR THE UL94V-0 UL REGISTERED MATERIAL ID NUMBER" at 288.569,26.397 h1.52
  text "ADDITIONAL REQUIREMENTS:" at 287.87,22.094 h1.52
  text "MICROSECTION:" at 289.769,19.373 h1.52
  text "YES" at 312.775,19.373 h1.52
  text "REQUIRED" at 334.657,15.707 h1.52
  text "BARE BOARD ELEC. TEST:" at 289.769,15.634 h1.52
  text "NONE" at 322.935,15.634 h1.52
  text "X" at 331.66,15.634 h1.52
  text "PER ORDER" at 349.693,15.634 h1.52
  text "XX MIL VIAS REQUIRE NON-CONDUCTIVE FILL AND PLANARIZE" at 294.04,10.428 h1.5
  text "XX MIL VIAS REQUIRE CONDUCTIVE FILL AND PLANARIZE" at 294.243,7.787 h1.52
  text "OUTER XX MIL VIAS REQUIRE 50 OHM SINGLE-ENDED IMPEDANCE" at 294.218,3.637 h1.47
  text "LAYER 2 & 3 (INNER LAYERS) XX MIL WIDE, XX MIL SPACE / TRACES REQUIRE 100 OHM DIFFERENTIAL IMPEDANCE" at 294.015,-2.35 h1.52
M11 Gerber Information:
  lines w0.254: -7.417,-48.626 160.223,-48.626 ; -7.417,-43.462 160.274,-43.462 ; -7.417,-38.297 -7.417,-53.791 94.31,-53.791 160.274,-53.791 160.274,-38.297 -7.404,-38.297 -7.404,-53.791 32.614,-53.791 ; 55.194,-53.791 55.194,-38.297 ; 87.376,-43.462 87.376,-38.297 ; 108.712,-43.462 108.712,-38.297 ; 124.511,-53.956 124.511,-48.804
  text "ALL ARTWORK VIEWED FROM TOP SIDE" at -5.804,-41.654 h1.52
  text "BOARD #:" at 57.099,-41.654 h1.52
  text ".PRJ_Number" at 70.955,-41.654 h1.52
  text "REV:" at 92.405,-41.654 h1.52
  text ".PCB_Rev" at 99.809,-41.654 h1.52
  text "SVN REV:" at 113.69,-41.654 h1.52
  text ".VersionControl_RevNumber" at 126.543,-41.654 h1.52
  text "LAYER NAME =" at -5.804,-46.806 h1.52
  text "PLOT NAME =" at -5.804,-52.034 h1.52
  text ".plot_File_Name" at 14.656,-52.034 h1.52
  text "GENERATED    :" at 57.15,-52.034 h1.52
  text ".Print_Date" at 79.235,-52.034 h1.52
  text ".Print_Time" at 97.752,-52.034 h1.52
  text "TEXAS INSTRUMENTS" at 129.87,-52.034 h1.52
M12 Stackup:
  drawing of 295 lines, arcs and shapes, not listed
  text ".Layer_Name" at 100,38 h1.52
  text "Layer" at 101.715,34.48 h1.52
  text "Name" at 112.126,34.48 h1.52
  text "Material" at 135.742,34.48 h1.52
  text "Thickness" at 157.58,34.48 h1.52
  text "Constant" at 174.086,34.48 h1.52
  text "Board Layer Stack" at 188.56,34.48 h1.52
  text "1" at 101.715,31.432 h1.52
  text "Top Overlay" at 112.126,31.432 h1.52
  text "2" at 101.715,28.384 h1.52
  text "Top Solder" at 112.126,28.384 h1.52
  text "Solder Resist" at 135.742,28.384 h1.52
  text "0.40mil" at 157.58,28.384 h1.52
  text "3.5" at 174.086,28.384 h1.52
  text "3" at 101.715,25.336 h1.52
  text "Top Layer" at 112.126,25.336 h1.52
  text "Copper" at 135.742,25.336 h1.52
  text "1.40mil" at 157.58,25.336 h1.52
  text "4" at 101.715,22.288 h1.52
  text "Dielectric1" at 112.126,22.288 h1.52
  text "FR-4" at 135.742,22.288 h1.52
  text "8.00mil" at 157.58,22.288 h1.52
  text "4.2" at 174.086,22.288 h1.52
  text "5" at 101.715,19.241 h1.52
  text "Mid-Layer 1" at 112.126,19.241 h1.52
  text "Copper" at 135.742,19.241 h1.52
  text "1.40mil" at 157.58,19.241 h1.52
  text "6" at 101.715,16.192 h1.52
  text "Dielectric3" at 112.126,16.192 h1.52
  text "FR-4" at 135.742,16.192 h1.52
  text "39.60mil" at 157.58,16.192 h1.52
  text "4.2" at 174.086,16.192 h1.52
  text "7" at 101.715,13.144 h1.52
  text "Mid-Layer 2" at 112.126,13.144 h1.52
  text "Copper" at 135.742,13.144 h1.52
  text "1.40mil" at 157.58,13.144 h1.52
  text "8" at 101.715,10.096 h1.52
  text "Dielectric2" at 112.126,10.096 h1.52
  text "FR-4" at 135.742,10.096 h1.52
  text "8.00mil" at 157.58,10.096 h1.52
  text "4.2" at 174.086,10.096 h1.52
  text "9" at 101.715,7.048 h1.52
  text "Bottom Layer" at 112.126,7.048 h1.52
  text "Copper" at 135.742,7.048 h1.52
  text "1.40mil" at 157.58,7.048 h1.52
  text "10" at 101.715,4 h1.52
  text "Bottom Solder" at 112.126,4 h1.52
  text "Solder Resist" at 135.742,4 h1.52
  text "0.40mil" at 157.58,4 h1.52
  text "3.5" at 174.086,4 h1.52
  text "11" at 101.715,0.953 h1.52
  text "Bottom Overlay" at 112.126,0.953 h1.52
M13 Component Bodies Top:
  text ".Layer_Name" at 14.656,-46.806 h1.52
M14 Component Bodies Bottom:
  text ".Layer_Name" at 14.656,-46.806 h1.52
M15 Courtyards Top:
  text ".Layer_Name" at 14.656,-46.806 h1.52
M16 Courtyards Bottom:
  text ".Layer_Name" at 14.656,-46.806 h1.52
Drill Drawing:
  drawing of 184 lines, arcs and shapes, not listed
  text "Symbol" at 2.44,161.974 h1.8
  text "Count" at 13.88,161.974 h1.8
  text "Hole Size" at 26.292,161.974 h1.8
  text "Plated" at 51.223,161.974 h1.8
  text "Hole Type" at 61.146,161.974 h1.8
  text "Drill Layer Pair" at 75.876,161.974 h1.8
  text "Via/Pad" at 106.692,161.974 h1.8
  text "Pad Shape" at 118.971,161.974 h1.8
  text "Template" at 135.021,161.974 h1.8
  text "Hole Tolerance (+)" at 159.795,161.974 h1.8
  text "Hole Length" at 192.66,161.974 h1.8
  text "Routed Path Length" at 216.491,161.974 h1.8
  text "2" at 13.88,158.224 h1.5
  text "0.200mm (7.87mil)" at 26.292,158.224 h1.5
  text "PTH" at 51.223,158.224 h1.5
  text "Round" at 61.146,158.224 h1.5
  text "Top Layer - Bottom Layer" at 75.876,158.224 h1.5
  text "Via" at 106.692,158.224 h1.5
  text "Rounded" at 118.971,158.224 h1.5
  text "v50h20" at 135.021,158.224 h1.5
  text "-" at 192.66,158.224 h1.5
  text "-" at 216.491,158.224 h1.5
  text "579" at 13.88,154.474 h1.5
  text "0.254mm (10.00mil)" at 26.292,154.474 h1.5
  text "PTH" at 51.223,154.474 h1.5
  text "Round" at 61.146,154.474 h1.5
  text "Top Layer - Bottom Layer" at 75.876,154.474 h1.5
  text "Via" at 106.692,154.474 h1.5
  text "Rounded" at 118.971,154.474 h1.5
  text "(Mixed)" at 135.021,154.474 h1.5
  text "-" at 192.66,154.474 h1.5
  text "-" at 216.491,154.474 h1.5
  text "A" at 1.713,154.224 h1.67
  text "12" at 13.88,150.724 h1.5
  text "0.300mm (11.81mil)" at 26.292,150.724 h1.5
  text "PTH" at 51.223,150.724 h1.5
  text "Round" at 61.146,150.724 h1.5
  text "Top Layer - Bottom Layer" at 75.876,150.724 h1.5
  text "Via" at 106.692,150.724 h1.5
  text "Rounded" at 118.971,150.724 h1.5
  text "(Mixed)" at 135.021,150.724 h1.5
  text "-" at 192.66,150.724 h1.5
  text "-" at 216.491,150.724 h1.5
  text "28" at 13.88,146.974 h1.5
  text "0.508mm (20.00mil)" at 26.292,146.974 h1.5
  text "PTH" at 51.223,146.974 h1.5
  text "Round" at 61.146,146.974 h1.5
  text "Top Layer - Bottom Layer" at 75.876,146.974 h1.5
  text "Via" at 106.692,146.974 h1.5
  text "Rounded" at 118.971,146.974 h1.5
  text "v114h51m0mx0" at 135.021,146.974 h1.5
  text "-" at 192.66,146.974 h1.5
  text "-" at 216.491,146.974 h1.5
  text "B" at 1.713,146.724 h1.67
  text "2" at 13.88,143.224 h1.5
  text "0.600mm (23.62mil)" at 26.292,143.224 h1.5
  text "PTH" at 51.223,143.224 h1.5
  text "Slot" at 61.146,143.224 h1.5
  text "Top Layer - Bottom Layer" at 75.876,143.224 h1.5
  text "Pad" at 106.692,143.224 h1.5
  text "Rounded" at 118.971,143.224 h1.5
  text "r80_200h60_130r100" at 135.021,143.224 h1.5
  text "1.300mm (51.18mil)" at 192.66,143.224 h1.5
  text "0.700mm (27.56mil)" at 216.491,143.224 h1.5
  text "6" at 13.88,139.474 h1.5
  text "0.610mm (24.00mil)" at 26.292,139.474 h1.5
  text "PTH" at 51.223,139.474 h1.5
  text "Round" at 61.146,139.474 h1.5
  text "Top Layer - Bottom Layer" at 75.876,139.474 h1.5
  text "Pad" at 106.692,139.474 h1.5
  text "(Mixed)" at 118.971,139.474 h1.5
  text "(Mixed)" at 135.021,139.474 h1.5
  text "-" at 192.66,139.474 h1.5
  text "-" at 216.491,139.474 h1.5
  text "2" at 13.88,135.724 h1.5
  text "0.700mm (27.56mil)" at 26.292,135.724 h1.5
  text "PTH" at 51.223,135.724 h1.5
  text "Slot" at 61.146,135.724 h1.5
  text "Top Layer - Bottom Layer" at 75.876,135.724 h1.5
  text "Pad" at 106.692,135.724 h1.5
  text "Rounded" at 118.971,135.724 h1.5
  text "r105_130h70_85r100" at 135.021,135.724 h1.5
  text "0.850mm (33.47mil)" at 192.66,135.724 h1.5
  text "0.150mm (5.91mil)" at 216.491,135.724 h1.5
  text "3" at 13.88,131.974 h1.5
  text "0.813mm (32.00mil)" at 26.292,131.974 h1.5
  text "PTH" at 51.223,131.974 h1.5
  text "Round" at 61.146,131.974 h1.5
  text "Top Layer - Bottom Layer" at 75.876,131.974 h1.5
  text "Pad" at 106.692,131.974 h1.5
  text "(Mixed)" at 118.971,131.974 h1.5
  text "(Mixed)" at 135.021,131.974 h1.5
  text "-" at 192.66,131.974 h1.5
  text "-" at 216.491,131.974 h1.5
  text "4" at 13.88,128.224 h1.5
  text "0.850mm (33.47mil)" at 26.292,128.224 h1.5
  text "PTH" at 51.223,128.224 h1.5
  text "Round" at 61.146,128.224 h1.5
  text "Top Layer - Bottom Layer" at 75.876,128.224 h1.5
  text "Pad" at 106.692,128.224 h1.5
  text "(Mixed)" at 118.971,128.224 h1.5
  text "(Mixed)" at 135.021,128.224 h1.5
  text "-" at 192.66,128.224 h1.5
  text "-" at 216.491,128.224 h1.5
  text "20" at 13.88,124.474 h1.5
  text "1.000mm (39.37mil)" at 26.292,124.474 h1.5
  text "PTH" at 51.223,124.474 h1.5
  text "Round" at 61.146,124.474 h1.5
  text "Top Layer - Bottom Layer" at 75.876,124.474 h1.5
  text "Pad" at 106.692,124.474 h1.5
  text "(Mixed)" at 118.971,124.474 h1.5
  text "(Mixed)" at 135.021,124.474 h1.5
  text "-" at 192.66,124.474 h1.5
  text "-" at 216.491,124.474 h1.5
  text "22" at 13.88,120.724 h1.5
  text "1.016mm (40.00mil)" at 26.292,120.724 h1.5
  text "PTH" at 51.223,120.724 h1.5
  text "Round" at 61.146,120.724 h1.5
  text "Top Layer - Bottom Layer" at 75.876,120.724 h1.5
  text "Pad" at 106.692,120.724 h1.5
  text "(Mixed)" at 118.971,120.724 h1.5
  text "(Mixed)" at 135.021,120.724 h1.5
  text "-" at 192.66,120.724 h1.5
  text "-" at 216.491,120.724 h1.5
  text "2" at 13.88,116.974 h1.5
  text "1.092mm (43.00mil)" at 26.292,116.974 h1.5
  text "PTH" at 51.223,116.974 h1.5
  text "Round" at 61.146,116.974 h1.5
  text "Top Layer - Bottom Layer" at 75.876,116.974 h1.5
  text "Pad" at 106.692,116.974 h1.5
  text "Rounded" at 118.971,116.974 h1.5
  text "c175h109" at 135.021,116.974 h1.5
  text "-" at 192.66,116.974 h1.5
  text "-" at 216.491,116.974 h1.5
  text "12" at 13.88,113.224 h1.5
  text "1.270mm (50.00mil)" at 26.292,113.224 h1.5
  text "PTH" at 51.223,113.224 h1.5
  text "Round" at 61.146,113.224 h1.5
  text "Top Layer - Bottom Layer" at 75.876,113.224 h1.5
  text "Pad" at 106.692,113.224 h1.5
  text "(Mixed)" at 118.971,113.224 h1.5
  text "(Mixed)" at 135.021,113.224 h1.5
  text "-" at 192.66,113.224 h1.5
  text "-" at 216.491,113.224 h1.5
  text "2" at 13.88,109.474 h1.5
  text "3.000mm (118.11mil)" at 26.292,109.474 h1.5
  text "PTH" at 51.223,109.474 h1.5
  text "Round" at 61.146,109.474 h1.5
  text "Top Layer - Bottom Layer" at 75.876,109.474 h1.5
  text "Pad" at 106.692,109.474 h1.5
  text "Rounded" at 118.971,109.474 h1.5
  text "c600h300(Tol545461)" at 135.021,109.474 h1.5
  text "5454.608mm (214748.34mil)" at 159.795,109.474 h1.5
  text "-" at 192.66,109.474 h1.5
  text "-" at 216.491,109.474 h1.5
  text "4" at 13.88,105.724 h1.5
  text "3.250mm (127.95mil)" at 26.292,105.724 h1.5
  text "PTH" at 51.223,105.724 h1.5
  text "Round" at 61.146,105.724 h1.5
  text "Top Layer - Bottom Layer" at 75.876,105.724 h1.5
  text "Via" at 106.692,105.724 h1.5
  text "Rounded" at 118.971,105.724 h1.5
  text "v600h325" at 135.021,105.724 h1.5
  text "-" at 192.66,105.724 h1.5
  text "-" at 216.491,105.724 h1.5
  text "700 Total" at 13.88,101.974 h1.5
  text "Slot definitions :" at 2.44,98.349 h1.5
  text "Routed Path Length" at 20.826,98.349 h1.5
  text "= Calculated from tool start centre position to tool end centre position." at 42.761,98.349 h1.5
  text "Hole Length" at 20.826,95.85 h1.5
  text "= Routed Path Length + Tool Size = Slot length as defined in the PCB layout" at 34.199,95.85 h1.5
  text ".Layer_Name" at 14.656,-46.806 h1.52
Grids:
  lines w0.2: 57.5,37.5 62.5,37.5 ; 60,35 60,40
  text ".Layer_Name" at 14.656,-46.806 h1.52

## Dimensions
0,-0.5 to 95,-0.5 on M2 Board Dimensions
-1.625,0 to -1.5,85 on M2 Board Dimensions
